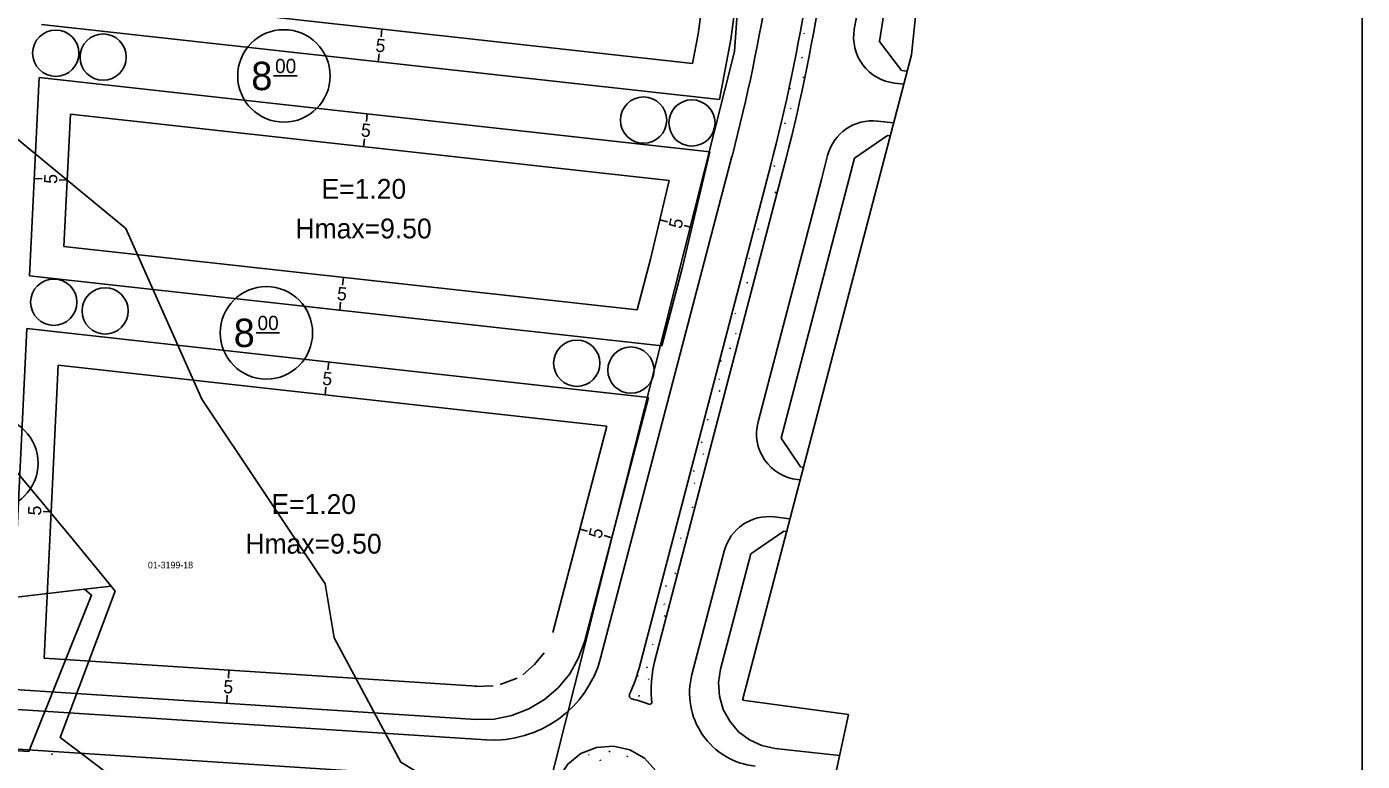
# Model space of a CAD drawing. Extents: x 419396 to 421519, y 4453567 to 4456767.
# Drawn here: x 421316.3 to 421518.6, y 4454614.7 to 4454725.9 of the extents above; entities that cross this region are included whole.
import ezdxf

# ---------------------------------------------------------------- set-up
doc = ezdxf.new("R2010")
doc.units = 0
for name, color, linetype in [('0_KADASTRO', 7, 'Continuous'), ('Level 20', 7, 'Continuous'), ('Level 28', 7, 'Continuous'), ('Level 29', 7, 'Continuous'), ('Level 30', 7, 'Continuous'), ('Level 41', 7, 'Continuous'), ('Level 55', 7, 'Continuous'), ('Level 58', 7, 'Continuous'), ('Level 62', 7, 'Continuous'), ('Level 9', 7, 'Continuous'), ('Y_Lejant', 7, 'Continuous')]:
    doc.layers.add(name, color=color, linetype=linetype)

msp = doc.modelspace()

# ---------------------------------------------------------------- linework, layer by layer
at = {"layer": '0_KADASTRO'}
for points in [[(421297.3, 4454718.68), (421298.33, 4454743.86), (421298.65, 4454753.52), (421298.8, 4454768.82), (421298.12, 4454819), (421299.79, 4454847.06), (421309.91, 4454834.93), (421332.63, 4454808.99), (421350.71, 4454801.96), (421374.76, 4454802.88), (421400.86, 4454807.28), (421429.39, 4454805.15), (421423.5, 4454722.17), (421393.26, 4454602.31), (421372.96, 4454614.59), (421362.83, 4454633.4), (421361.48, 4454641.58), (421342.8, 4454669.52), (421331.29, 4454695.38), (421310.81, 4454712.23)], [(421297.3, 4454718.68), (421298.33, 4454743.86), (421298.65, 4454753.52), (421298.8, 4454768.82), (421298.12, 4454819), (421299.79, 4454847.06), (421309.91, 4454834.93), (421332.63, 4454808.99), (421350.71, 4454801.96), (421374.76, 4454802.88), (421400.86, 4454807.28), (421429.39, 4454805.15), (421423.5, 4454722.17), (421393.26, 4454602.31), (421372.96, 4454614.59), (421362.83, 4454633.4), (421361.48, 4454641.58), (421342.8, 4454669.52), (421331.29, 4454695.38), (421310.81, 4454712.23)], [(421297.13, 4454679.68), (421301.26, 4454686.4), (421298.07, 4454709.08), (421297.3, 4454718.68), (421310.81, 4454712.23), (421331.29, 4454695.38), (421342.8, 4454669.52), (421361.48, 4454641.58), (421362.83, 4454633.4), (421372.96, 4454614.59), (421393.26, 4454602.31), (421380.9, 4454570.22), (421362.08, 4454588), (421340.49, 4454603.84), (421321.35, 4454618.34), (421329.67, 4454640.5), (421329.07, 4454641.24), (421323.38, 4454648.19)], [(421297.13, 4454679.68), (421301.26, 4454686.4), (421298.07, 4454709.08), (421297.3, 4454718.68), (421310.81, 4454712.23), (421331.29, 4454695.38), (421342.8, 4454669.52), (421361.48, 4454641.58), (421362.83, 4454633.4), (421372.96, 4454614.59), (421393.26, 4454602.31), (421380.9, 4454570.22), (421362.08, 4454588), (421340.49, 4454603.84), (421321.35, 4454618.34), (421329.67, 4454640.5), (421329.07, 4454641.24), (421323.38, 4454648.19)], [(421268.03, 4454634.05), (421269.69, 4454637.2), (421277.56, 4454646.58), (421290.65, 4454667.07), (421297.13, 4454679.68), (421323.38, 4454648.19), (421329.07, 4454641.24), (421325.01, 4454640.76), (421300.09, 4454637.83), (421285.2, 4454636.07), (421270.3, 4454634.32)], [(421268.03, 4454634.05), (421269.69, 4454637.2), (421277.56, 4454646.58), (421290.65, 4454667.07), (421297.13, 4454679.68), (421323.38, 4454648.19), (421329.07, 4454641.24), (421325.01, 4454640.76), (421300.09, 4454637.83), (421285.2, 4454636.07), (421270.3, 4454634.32)], [(421300.09, 4454637.83), (421325.01, 4454640.76), (421326.11, 4454639.88), (421316.58, 4454616.19), (421302.91, 4454617.12)], [(421300.09, 4454637.83), (421325.01, 4454640.76), (421326.11, 4454639.88), (421316.58, 4454616.19), (421302.91, 4454617.12)]]:
    msp.add_lwpolyline(points, close=True, dxfattribs=at)
at = {"layer": 'Level 20'}
for p, q in [((421419.92, 4454738.9), (421417.97, 4454724.8)), ((421417.14, 4454720.35), (421323.77, 4454730.7)), ((421370.08, 4454725.57), (421369.95, 4454724.37)), ((421417.97, 4454724.8), (421417.14, 4454720.35)), ((421369.53, 4454720.6), (421369.66, 4454721.79)), ((421321.93, 4454692.67), (421322.9, 4454712.69)), ((421322.9, 4454712.69), (421413.58, 4454702.63)), ((421367.86, 4454712.73), (421367.73, 4454711.54)), ((421367.31, 4454707.76), (421367.45, 4454708.96)), ((421317.42, 4454702.92), (421318.61, 4454702.87)), ((421322.41, 4454702.68), (421321.21, 4454702.74)), ((421413.58, 4454702.63), (421410.76, 4454690.73)), ((421412.17, 4454696.68), (421413.34, 4454696.4)), ((421417.04, 4454695.53), (421415.87, 4454695.8)), ((421408.75, 4454683.05), (421321.93, 4454692.67)), ((421410.76, 4454690.73), (421408.75, 4454683.05)), ((421364.24, 4454687.98), (421364.1, 4454686.79)), ((421363.69, 4454683.01), (421363.82, 4454684.21)), ((421362.02, 4454675.15), (421361.89, 4454673.96)), ((421318.91, 4454630.33), (421321.05, 4454674.66)), ((421321.05, 4454674.66), (421404.14, 4454665.45)), ((421361.47, 4454670.18), (421361.6, 4454671.37)), ((421404.14, 4454665.45), (421395.96, 4454634.23)), ((421319.98, 4454652.5), (421318.78, 4454652.55)), ((421400.05, 4454649.84), (421401.21, 4454649.54)), ((421404.89, 4454648.57), (421403.73, 4454648.88)), ((421394.66, 4454631.15), (421393.18, 4454629.36)), ((421384.42, 4454626.08), (421318.91, 4454630.33)), ((421346.9, 4454628.51), (421346.82, 4454627.32)), ((421393.18, 4454629.36), (421391.43, 4454627.84)), ((421390.54, 4454627.31), (421387.97, 4454626.33)), ((421346.58, 4454623.52), (421346.65, 4454624.72)), ((421386.95, 4454626.13), (421384.2, 4454626.07))]:
    msp.add_line(p, q, dxfattribs=at)
at = {"layer": 'Level 28'}
for p, q in [((421448.79, 4454719.26), (421445.44, 4454723.67)), ((421313.68, 4454625.66), (421316.32, 4454680.21))]:
    msp.add_line(p, q, dxfattribs=at)
at = {"layer": 'Level 29'}
for p, q in [((421445.44, 4454723.67), (421449.3, 4454748.39)), ((421425.58, 4454743.31), (421422.91, 4454723.99)), ((421421.2, 4454714.87), (421318.54, 4454726.25)), ((421422.91, 4454723.99), (421421.2, 4454714.87)), ((421316.7, 4454688.22), (421318.16, 4454718.24)), ((421318.16, 4454718.24), (421419.74, 4454706.98)), ((421449.64, 4454719.17), (421448.8, 4454719.27)), ((421441.64, 4454706.02), (421446.63, 4454709.44)), ((421446.63, 4454709.45), (421447.07, 4454709.4)), ((421419.74, 4454706.98), (421415.61, 4454689.52)), ((421430.54, 4454663.63), (421441.64, 4454706.02)), ((421415.61, 4454689.52), (421412.49, 4454677.6)), ((421412.49, 4454677.6), (421316.7, 4454688.22)), ((421316.32, 4454680.21), (421410.44, 4454669.78)), ((421410.44, 4454669.78), (421400.8, 4454632.96)), ((421433.5, 4454659.31), (421430.54, 4454663.63)), ((421433.93, 4454659.27), (421433.5, 4454659.31)), ((421425.95, 4454646.12), (421430.94, 4454649.54)), ((421430.94, 4454649.54), (421431.36, 4454649.49)), ((421421.38, 4454628.68), (421425.95, 4454646.12)), ((421400.8, 4454632.96), (421399.87, 4454630.37)), ((421399.87, 4454630.37), (421398.52, 4454627.98)), ((421421.08, 4454626.64), (421421.38, 4454628.68)), ((421398.52, 4454627.98), (421396.77, 4454625.85)), ((421421.21, 4454624.58), (421421.08, 4454626.64)), ((421384.31, 4454621.07), (421313.68, 4454625.66)), ((421396.77, 4454625.85), (421394.69, 4454624.06)), ((421421.78, 4454622.59), (421421.21, 4454624.58)), ((421392.33, 4454622.65), (421389.76, 4454621.66)), ((421394.69, 4454624.06), (421392.33, 4454622.65)), ((421422.76, 4454620.78), (421421.78, 4454622.59)), ((421387.06, 4454621.13), (421384.31, 4454621.07)), ((421389.76, 4454621.66), (421387.06, 4454621.13)), ((421424.11, 4454619.21), (421422.76, 4454620.78)), ((421425.76, 4454617.97), (421424.11, 4454619.21)), ((421427.63, 4454617.11), (421425.76, 4454617.97)), ((421429.65, 4454616.67), (421427.63, 4454617.11)), ((421439.4, 4454615.6), (421429.65, 4454616.67))]:
    msp.add_line(p, q, dxfattribs=at)
at = {"layer": 'Level 41'}
for p, q in [((421433.97, 4454724.94), (421434.04, 4454724.83)), ((421433.69, 4454721.31), (421433.71, 4454721.15)), ((421433.86, 4454718.17), (421433.93, 4454718.33)), ((421431.87, 4454716.62), (421431.94, 4454716.51)), ((421431.94, 4454713.59), (421432.01, 4454713.48)), ((421431.09, 4454711.19), (421431.16, 4454711.35)), ((421429.41, 4454706.66), (421429.48, 4454706.55)), ((421429.47, 4454704.74), (421429.54, 4454704.9)), ((421429.65, 4454700.74), (421429.72, 4454700.9)), ((421427.03, 4454695.31), (421427.1, 4454695.2)), ((421425.67, 4454690.9), (421425.75, 4454690.79)), ((421425.4, 4454687.27), (421425.42, 4454687.11)), ((421425.57, 4454684.13), (421425.58, 4454684.17)), ((421423.58, 4454682.58), (421423.65, 4454682.47)), ((421423.64, 4454679.55), (421423.71, 4454679.44)), ((421422.79, 4454677.15), (421422.87, 4454677.31)), ((421421.36, 4454675.21), (421421.43, 4454675.37)), ((421421.12, 4454672.62), (421421.19, 4454672.51)), ((421421.18, 4454670.7), (421421.25, 4454670.86)), ((421419.37, 4454666.49), (421419.44, 4454666.38)), ((421418.48, 4454662.92), (421418.55, 4454663.07)), ((421418.74, 4454661.27), (421418.81, 4454661.16)), ((421417.27, 4454658.6), (421417.34, 4454658.76)), ((421417.38, 4454656.86), (421417.45, 4454656.75)), ((421417.11, 4454653.23), (421417.13, 4454653.07)), ((421415.28, 4454648.54), (421415.35, 4454648.43)), ((421415.35, 4454645.51), (421415.42, 4454645.4)), ((421414.5, 4454643.11), (421414.57, 4454643.27)), ((421413.06, 4454641.17), (421413.13, 4454641.33)), ((421412.83, 4454638.58), (421412.9, 4454638.47)), ((421412.88, 4454636.66), (421412.96, 4454636.82)), ((421411.07, 4454632.45), (421411.15, 4454632.34)), ((421410.19, 4454628.88), (421410.26, 4454629.03)), ((421408.81, 4454627.7), (421408.83, 4454627.54)), ((421410.44, 4454627.23), (421410.51, 4454627.12)), ((421408.98, 4454624.56), (421409.05, 4454624.72)), ((421320.09, 4454615.73), (421320.16, 4454615.89)), ((421401.39, 4454615.75), (421401.46, 4454615.64)), ((421403.15, 4454614.96), (421403.17, 4454614.8)), ((421404.52, 4454616.13), (421404.59, 4454616.29)), ((421407.22, 4454615.4), (421407.29, 4454615.56))]:
    msp.add_line(p, q, dxfattribs=at)
at = {"layer": 'Level 55'}
for centre in [(421320.68, 4454721.9), (421327.86, 4454721.31), (421409.71, 4454711.78), (421417.04, 4454711.34), (421320.38, 4454684.21), (421328.16, 4454682.89), (421399.59, 4454674.97), (421407.8, 4454673.94)]:
    msp.add_circle(centre, 3.5, dxfattribs=at)
at = {"layer": 'Level 58'}
for p, q in [((421353.68, 4454718.46), (421357.24, 4454718.46)), ((421351.02, 4454679.57), (421354.57, 4454679.57))]:
    msp.add_line(p, q, dxfattribs=at)
for centre in [(421355.24, 4454718.46), (421352.58, 4454679.57), (421311.02, 4454659.85)]:
    msp.add_circle(centre, 7, dxfattribs=at)
at = {"layer": 'Level 62'}
for p, q in [((421441.63, 4454725.55), (421441.95, 4454727.35)), ((421447.74, 4454717.38), (421449.12, 4454717.22)), ((421445.16, 4454711.64), (421447.59, 4454711.36)), ((421403.26, 4454630.53), (421423.1, 4454706.28)), ((421436.66, 4454702.77), (421437.59, 4454706.41)), ((421409.02, 4454628.82), (421428.92, 4454704.8)), ((421411.34, 4454629.79), (421430.85, 4454704.29)), ((421427.05, 4454666.09), (421436.66, 4454702.77)), ((421433.03, 4454657.36), (421433.42, 4454657.32)), ((421429.49, 4454651.72), (421431.88, 4454651.45)), ((421417.04, 4454627.88), (421421.93, 4454646.54)), ((421408.86, 4454628.24), (421409.02, 4454628.82)), ((421411.12, 4454628.6), (421410.99, 4454627.7)), ((421411.34, 4454629.79), (421411.12, 4454628.6)), ((421408.05, 4454625.95), (421408.28, 4454626.51)), ((421408.28, 4454626.51), (421408.49, 4454627.08)), ((421408.49, 4454627.08), (421408.68, 4454627.66)), ((421408.68, 4454627.66), (421408.86, 4454628.24)), ((421410.91, 4454626.79), (421410.87, 4454625.88)), ((421410.99, 4454627.7), (421410.91, 4454626.79)), ((421385.84, 4454617.97), (421262.52, 4454625.98)), ((421407.59, 4454624.9), (421407.82, 4454625.39)), ((421407.82, 4454625.39), (421408.05, 4454625.95)), ((421410.87, 4454625.88), (421410.88, 4454624.97)), ((421410.88, 4454624.97), (421410.93, 4454624.06)), ((421408.25, 4454624.1), (421407.95, 4454624.16)), ((421408.72, 4454623.97), (421408.25, 4454624.1)), ((421409.19, 4454623.84), (421408.72, 4454623.97)), ((421409.66, 4454623.69), (421409.19, 4454623.84)), ((421410.12, 4454623.53), (421409.66, 4454623.69)), ((421410.51, 4454623.37), (421410.12, 4454623.53)), ((421410.93, 4454624.06), (421410.96, 4454623.72)), ((421385.65, 4454611.97), (421262.45, 4454619.97))]:
    msp.add_line(p, q, dxfattribs=at)
msp.add_lwpolyline([(421413.05, 4454608.49), (421412.67, 4454611.01), (421411.57, 4454613.31), (421409.83, 4454615.18), (421407.62, 4454616.45), (421405.14, 4454617.02), (421402.6, 4454616.83), (421400.23, 4454615.9), (421398.23, 4454614.31), (421396.8, 4454612.2), (421396.04, 4454609.76), (421396.04, 4454607.22), (421396.8, 4454604.78), (421398.23, 4454602.67), (421400.23, 4454601.08), (421402.6, 4454600.15), (421405.14, 4454599.96), (421407.62, 4454600.53), (421409.83, 4454601.8), (421411.57, 4454603.67), (421412.67, 4454605.97), (421413.05, 4454608.49)], dxfattribs=at)
for centre, radius, start, end in [((421161.19, 4454774.89), 270.75, 345.3215, 351.1193), ((421161.93, 4454774.74), 276, 345.3215, 351.1193), ((421161.93, 4454774.74), 278, 345.3215, 351.1193), ((421448.52, 4454724.34), 7, 170.0322, 263.5428), ((421444.37, 4454704.68), 7, 83.5428, 165.6839), ((421433.82, 4454664.32), 7, 165.3215, 263.5428), ((421428.7, 4454644.77), 7, 83.5428, 165.3215), ((421386.94, 4454634.81), 16.87, 266.2833, 345.3215), ((421427.81, 4454625.06), 11.13, 165.3215, 263.7521), ((421408.07, 4454624.68), 0.526, 155.3409, 257.3558), ((421410.63, 4454623.68), 0.333, 248.6498, 5.7934)]:
    msp.add_arc(centre, radius, start, end, dxfattribs=at)
at = {"layer": 'Level 9'}
for p, q in [((421450.29, 4454721.67), (421457.23, 4454788.95)), ((421424.68, 4454624), (421450.29, 4454721.67)), ((421440.74, 4454621.83), (421424.68, 4454624)), ((421434.23, 4454591.45), (421440.74, 4454621.83))]:
    msp.add_line(p, q, dxfattribs=at)
at = {"layer": 'Y_Lejant'}
msp.add_lwpolyline([(420209.76, 4455704.6), (421518.56, 4455690.86), (421518.56, 4454302.65), (420195.09, 4454316.54)], close=True, dxfattribs=at)

# ---------------------------------------------------------------- texts
at = {"layer": '0_KADASTRO'}
msp.add_text('01-3199-18', height=1, dxfattribs=at).set_placement((421334.64, 4454643.93))
msp.add_text('01-3199-18', height=1, dxfattribs=at).set_placement((421334.64, 4454643.93))
at = {"layer": 'Level 20'}
for rotation, p in [(353.672, (421369.03, 4454722.16)), (353.672, (421366.82, 4454709.33)), (87.2286, (421320.88, 4454702.09)), (76.6855, (421415.42, 4454695.22)), (353.672, (421363.19, 4454684.58)), (353.672, (421360.97, 4454671.74)), (87.2286, (421318.45, 4454651.9)), (75.3215, (421403.27, 4454648.31)), (356.2833, (421346.01, 4454625.06))]:
    msp.add_text('5', height=2, rotation=rotation, dxfattribs=at).set_placement(p)
at = {"layer": 'Level 30'}
for s, p in [('E=1.20', (421360.93, 4454699.87)), ('Hmax=9.50', (421356.99, 4454693.87)), ('E=1.20', (421353.34, 4454652.16)), ('Hmax=9.50', (421349.41, 4454646.16))]:
    msp.add_text(s, height=3, dxfattribs=at).set_placement(p)
at = {"layer": 'Level 58'}
for s, height, p in [('8', 4.3, (421350.29, 4454716.31)), ('00', 2.152, (421353.9, 4454718.89)), ('8', 4.3, (421347.63, 4454677.42)), ('00', 2.152, (421351.24, 4454680))]:
    msp.add_text(s, height=height, dxfattribs=at).set_placement(p)

doc.saveas('drawing.dxf')
